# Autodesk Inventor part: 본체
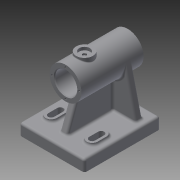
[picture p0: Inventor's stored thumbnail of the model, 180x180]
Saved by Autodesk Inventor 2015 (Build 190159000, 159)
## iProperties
Created: 2022-06
Part Number: 본체
Material: 일반
Document SubType Name: Modeling
Designer: 102566
Density: 1 g/cm^3
Appearance: 기본값
Author: 102566
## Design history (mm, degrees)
sketch "스케치1"
  geometry: L1 (43, -50)-(-43, -50); L2 (-43, -50)-(-43, 50); L3 (-43, 50)-(43, 50); L4 (43, 50)-(43, -50); L5 (43, -50)-(-43, 50); L6 (-43, -50)-(43, 50); 1 further point
  constraints: 12 end point, 2 midpoint, 2 parallel, 1 horizontal, 1 perpendicular
  dimensions: "d0" = 86 distance of L2.end L3.end; "d1" = 100 distance of L1.end L2.end
extrude "돌출1" new body sketch "스케치1" distance "d2" = 15; taper "d3" = 0 deg
sketch "스케치3"
  geometry: L1 (-32, 93)-(50, 93); L2 (50, 93)-(50, 72); L3 (50, 72)-(-32, 72); L4 (-32, 72)-(-32, 93); L5 (50, 0)-(-50, 0) reference; L6 (50, 0)-(-50, 0) reference; L7 (50, 0)-(50, 15) reference; L8 (-50, 15)-(50, 15) reference; L9 (-50, 0)-(-50, 15) reference; 3 further points
  constraints: 8 end point, 2 midpoint, 2 parallel, 1 horizontal, 1 perpendicular, 1 vertical alignment
  dimensions: "d4" = 72 distance between parallel lines of L5 L3; "d5" = 21 distance between parallel lines of L3 L1; "d6" = 82 distance between parallel lines of L2 L4
revolve "회전1" sketch "스케치3" stored, may be unused: angle "d7" = 90 deg
node "작업 평면1"
sketch "스케치4"
  geometry: L1 (21, -32)-(-21, -32) reference; C1 r 11 at (0, -7); 1 further point
  constraints: 1 centre point, 1 vertical alignment
  dimensions: "d9" = 22 diameter of C1; "d10" = 25 distance from line of L1 C1.centre
extrude "돌출2" join sketch "스케치4" distance "d11" = 24; taper "d12" = 0 deg
node "작업 평면2"
sketch "스케치9"
  geometry: C1 r 21 at (0, 0) reference; C2 r 14.5 at (0, 0); 1 further point
  constraints: 1 centre point, 1 coincident
  dimensions: "d34" = 29 diameter of C2
extrude "돌출7" cut sketch "스케치9" distance "d35" = 62; taper "d36" = 0 deg
sketch "스케치10"
  geometry: C1 r 14.5 at (0, 0) reference; C2 r 11.5 at (0, 0); 1 further point
  constraints: 1 centre point, 1 coincident
  dimensions: "d37" = 23 diameter of C2
extrude "돌출8" cut sketch "스케치10" stored distance "d38" = 62; taper "d39" = 0 deg
sketch "스케치11"
  geometry: C1 r 11 at (0, 0) reference; 1 further point
hole "구멍1" sketch "스케치11" at (0, 0) diameter "d40" = 4.917; stored, may be unused: countersink angle "d44" = 90 deg, drill point angle "d46" = 118 deg; dims "d41" = 12, "d42" = 14, "d43" = 4, "d45" = 17.1
sketch "스케치12"
  geometry: C1 r 14.5 at (0, 0) reference; 2 further points
  constraints: 1 vertical alignment
  dimensions: "d47" = 18 distance of C1.centre point (0, 18)
hole "구멍2" sketch "스케치12" at (0, 18) diameter "d48" = 2.459; stored, may be unused: countersink angle "d52" = 90 deg, drill point angle "d54" = 118 deg; dims "d49" = 8, "d50" = 14, "d51" = 4, "d53" = 10
sketch "스케치13"
  geometry: L1 (-43, -50)-(43, -50) reference; L2 (-43, 50)-(-43, -50) reference; L3 (-27, -24)-(-27, -12); L4 (-20, -24)-(-20, -12); L5 (-34, -12)-(-34, -24); L6 (-23, -24)-(-23, -12); L7 (-31, -12)-(-31, -24); A1 r 7 centre (-27, -24) between (-34, -24) and (-20, -24); A2 r 7 centre (-27, -12) between (-20, -12) and (-34, -12); A3 r 4 centre (-27, -12) between (-23, -12) and (-31, -12); A4 r 4 centre (-27, -24) between (-31, -24) and (-23, -24); 2 further points
  constraints: 12 end point, 8 point on circle, 4 centre point, 4 tangent, 2 parallel, 1 midpoint, 1 vertical, 3 other
  dimensions: "d58" = 12 distance of L3.start L3.end; "d59" = 14 diameter of A2; "d60" = 26 distance from line of L1 L3.start; "d61" = 16 distance from line of point (-27, -18) L2; "d62" = 3 radial gap between concentric circles of A1 A4
extrude "돌출9" join sketch "스케치13" distance "d63" = 3; taper "d64" = 0 deg
extrude "돌출10" cut sketch "스케치13" stored distance "d65" = 3; taper "d66" = 0 deg
node "작업 평면4"
fillet "모깎기3" dims "d67" = 3
fillet "모깎기6" dims "d71" = 3
fillet "모깎기7" dims "d72" = 3
fillet "모깎기8" dims "d73" = 1
sketch "스케치14"
  geometry: L1 (0, 0)-(80, 0) reference; 3 further points
  constraints: 1 midpoint, 1 vertical alignment, 1 other
  dimensions: "d75" = 6 distance from line of L1 point (40, -6)
feature "엠보싱1" sketch "스케치14" dims "d76" = 0.5, "d77" = 0
chamfer "모따기1" distance "d78" = 1; stored, may be unused: second distance "d79" = 2, angle "d80" = 45 deg
sketch "스케치15"
  geometry: L1 (-5, 35)-(5, 35); L2 (5, 35)-(5, -35); L3 (5, -35)-(-5, -35); L4 (-5, -35)-(-5, 35); L5 (-40, -50)-(40, -50) reference; L6 (40, 50)-(-40, 50) reference; 1 further point
  constraints: 8 end point, 2 parallel, 1 horizontal, 1 perpendicular
  dimensions: "d81" = 15 distance between parallel lines of L5 L3; "d82" = 15 distance between parallel lines of L6 L1; "d83" = 5 distance from line of point (0, 0) L4; "d84" = 10 distance between parallel lines of L2 L4
extrude "돌출11" join sketch "스케치15" distance "d85" = 37.25; taper "d86" = 0 deg
feature "면 기울기2" dims angle "d87" = 20 deg
sketch "스케치16"
  geometry: L1 (5, 35)-(5, -35) reference; L2 (5, -35)-(-5, -35) reference; L3 (-5, -35)-(-5, 35) reference; L4 (-5, 35)-(5, 35) reference; L5 (17, -12)-(17, -24) reference; L6 (37, -24)-(37, -12) reference; L7 (-37, -12)-(-37, -24) reference; L8 (-17, -24)-(-17, -12) reference; L9 (-40, 47)-(40, 47) reference; L10 (-40, -47)-(-40, 47) reference; L11 (40, -47)-(-40, -47) reference; L12 (40, 47)-(40, -47) reference; A1 r 10 centre (27, -12) between (37, -12) and (17, -12) reference; A2 r 10 centre (27, -24) between (17, -24) and (37, -24) reference; A3 r 10 centre (-27, -12) between (-17, -12) and (-37, -12) reference; A4 r 10 centre (-27, -24) between (-37, -24) and (-17, -24) reference; 1 further point
sketch "스케치17"
  geometry: L1 (0, -12)-(0, 0) reference; L2 (0, 0)-(86, 0) reference; L3 (86, 0)-(86, -12) reference; L4 (83, -15)-(48, -15) reference; L5 (48, -15)-(38, -15) reference; L6 (38, -15)-(3, -15) reference; L7 (48, -15)-(48, -51.604) reference; L8 (38, -51.604)-(38, -15) reference; L9 (78, -15)-(63.441, -76.814); L10 (8, -15)-(22.559, -76.814); L11 (78, -15)-(8, -15); L12 (6, -15)-(26, -15) reference; C1 r 11.5 at (43, -72) reference; A1 r 3 centre (3, -12) between (0, -12) and (3, -15) reference; A2 r 3 centre (83, -12) between (83, -15) and (86, -12) reference; A3 r 21 centre (43, -72) between (38, -51.604) and (48, -51.604) reference; A4 r 21 centre (43, -72) between (48, -51.604) and (38, -51.604) reference; A5 r 21 centre (43, -72) between (63.441, -76.814) and (22.559, -76.814); 1 further point
  constraints: 6 end point, 2 point on circle, 2 point on line, 2 tangent, 1 centre point, 1 coincident, 1 collinear, 1 concentric
  dimensions: "d88" = 8 distance from line of L1 L10.start; "d90" = 8 distance from line of L3 L9.start
extrude "돌출12" join sketch "스케치17" distance "d91" = 10; taper "d92" = 0 deg
fillet "모깎기10" dims "d93" = 3
fillet "모깎기11" dims "d94" = 3
fillet "모깎기12" dims "d95" = 3
node "작업 평면6"
node "솔리드1"
pattern_circular "원형 패턴1" dims angle "d56" = 360 deg
mirror "대칭2"
mirror "대칭5"
node "투영된 루프1"
node "절단 모서리 투영3"
other parameters: "d8" = 72, "d25" = -15
